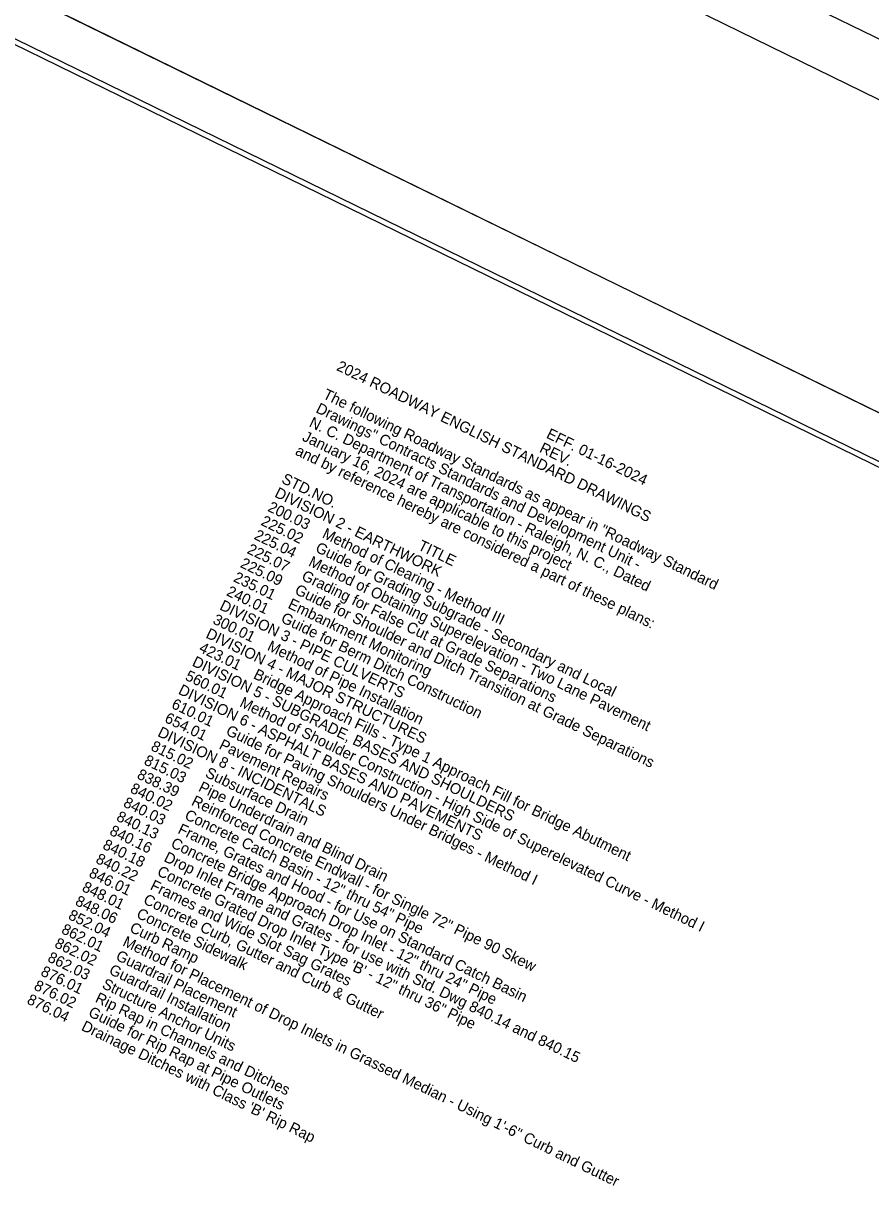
# Model space of a CAD drawing. Extents: x 1517888 to 1526099, y 633375 to 640181.
# Drawn here: x 1521738 to 1522517, y 634903 to 635991 of the extents above; entities that cross this region are included whole.
import ezdxf

# ---------------------------------------------------------------- set-up
doc = ezdxf.new("R2010")
doc.units = 0
for name, color, linetype in [('Default', 7, 'Continuous'), ('Sheet Cutting Line CELL', 7, 'Continuous'), ('Sheet Data Text CELL', 7, 'Continuous'), ('Sheet Plan CELL', 7, 'Continuous'), ('Sheet Plot Border Inside CELL', 7, 'Continuous'), ('Sheet Plot Border Outside CELL', 7, 'Continuous')]:
    doc.layers.add(name, color=color, linetype=linetype)

msp = doc.modelspace()

# ---------------------------------------------------------------- linework, layer by layer
at = {"layer": 'Default'}
msp.add_line((1521963.6, 636251.5), (1524989.1, 634771.8), dxfattribs=at)
at = {"layer": 'Sheet Cutting Line CELL'}
msp.add_line((1523118.1, 635342.8), (1520093.5, 636822.1), dxfattribs=at)
at = {"layer": 'Sheet Plan CELL'}
msp.add_lwpolyline([(1523067.8, 635317.3), (1520372.9, 636635.4), (1519450.2, 634748.9), (1522145.2, 633430.8)], close=True, dxfattribs=at)
at = {"layer": 'Sheet Plot Border Inside CELL'}
msp.add_lwpolyline([(1519172.2, 634879.3), (1522165.4, 633415.4), (1523092.5, 635310.8), (1520099.3, 636774.7)], close=True, dxfattribs=at)
at = {"layer": 'Sheet Plot Border Outside CELL'}
for points in [[(1525964.3, 636688.2), (1522938.8, 638168), (1521972.2, 636191.7), (1524997.7, 634712)], [(1519131.3, 634854.8), (1522155.9, 633375.5), (1523118.1, 635342.8), (1520093.5, 636822.1)]]:
    msp.add_lwpolyline(points, close=True, dxfattribs=at)

# ---------------------------------------------------------------- texts
at = {"layer": 'Sheet Data Text CELL'}
for s, p in [('2024 ROADWAY ENGLISH STANDARD DRAWINGS', (1522024.8, 635672.8)), ('The following Roadway Standards as appear in "Roadway Standard', (1522012.2, 635646.9)), ('Drawings" Contracts Standards and Development Unit -', (1522005.8, 635634)), ('N. C. Department of Transportation - Raleigh, N. C., Dated ', (1521999.5, 635621)), ('January 16, 2024 are applicable to this project', (1521993.2, 635608.1)), ('                                                      EFF. 01-16-2024', (1522037.5, 635698.7)), ('                                                      REV. ', (1522031.2, 635685.7)), ('and by reference hereby are considered a part of these plans:', (1521986.8, 635595.1)), ('STD.NO.                       TITLE', (1521974.2, 635569.2)), ('DIVISION 2 - EARTHWORK', (1521967.8, 635556.3)), ('200.03    Method of Clearing - Method III', (1521961.5, 635543.3)), ('225.02    Guide for Grading Subgrade - Secondary and Local', (1521955.2, 635530.4)), ('225.04    Method of Obtaining Superelevation - Two Lane Pavement', (1521948.9, 635517.5)), ('225.07    Grading for False Cut at Grade Separations', (1521942.5, 635504.5)), ('225.09    Guide for Shoulder and Ditch Transition at Grade Separations', (1521936.2, 635491.6)), ('235.01    Embankment Monitoring', (1521929.9, 635478.6)), ('240.01    Guide for Berm Ditch Construction', (1521923.5, 635465.7)), ('DIVISION 3 - PIPE CULVERTS', (1521917.2, 635452.7)), ('300.01    Method of Pipe Installation ', (1521910.9, 635439.8)), ('DIVISION 4 - MAJOR STRUCTURES', (1521904.5, 635426.8)), ('423.01    Bridge Approach Fills - Type 1 Approach Fill for Bridge Abutment', (1521898.2, 635413.9)), ('DIVISION 5 - SUBGRADE, BASES AND SHOULDERS', (1521891.9, 635401)), ('560.01    Method of Shoulder Construction - High Side of Superelevated Curve - Method I', (1521885.5, 635388)), ('DIVISION 6 - ASPHALT BASES AND PAVEMENTS', (1521879.2, 635375.1)), ('610.01    Guide for Paving Shoulders Under Bridges - Method I', (1521872.9, 635362.1)), ('654.01    Pavement Repairs', (1521866.6, 635349.2)), ('DIVISION 8 - INCIDENTALS', (1521860.2, 635336.2)), ('815.02    Subsurface Drain', (1521853.9, 635323.3)), ('815.03    Pipe Underdrain and Blind Drain', (1521847.6, 635310.3)), ('838.39    Reinforced Concrete Endwall - for Single 72" Pipe 90 Skew', (1521841.2, 635297.4)), ('840.02    Concrete Catch Basin - 12" thru 54" Pipe', (1521834.9, 635284.5)), ('840.03    Frame, Grates and Hood - for Use on Standard Catch Basin', (1521828.6, 635271.5)), ('840.13    Concrete Bridge Approach Drop Inlet - 12" thru 24" Pipe ', (1521822.2, 635258.6)), ('840.16    Drop Inlet Frame and Grates - for use with Std. Dwg 840.14 and 840.15', (1521815.9, 635245.6)), ('840.18    Concrete Grated Drop Inlet Type \'B\' - 12" thru 36" Pipe', (1521809.6, 635232.7)), ('840.22    Frames and Wide Slot Sag Grates', (1521803.2, 635219.7)), ('846.01    Concrete Curb, Gutter and Curb & Gutter', (1521796.9, 635206.8)), ('848.01    Concrete Sidewalk', (1521790.6, 635193.8)), ('848.06    Curb Ramp', (1521784.3, 635180.9)), ('852.04    Method for Placement of Drop Inlets in Grassed Median - Using 1\'-6" Curb and Gutter', (1521777.9, 635168)), ('862.01    Guardrail Placement', (1521771.6, 635155)), ('862.02    Guardrail Installation', (1521765.3, 635142.1)), ('862.03    Structure Anchor Units', (1521758.9, 635129.1)), ('876.01    Rip Rap in Channels and Ditches', (1521752.6, 635116.2)), ('876.02    Guide for Rip Rap at Pipe Outlets', (1521746.3, 635103.2)), ("876.04    Drainage Ditches with Class 'B' Rip Rap", (1521739.9, 635090.3))]:
    msp.add_text(s, height=10, rotation=333.9377, dxfattribs=at).set_placement(p)

doc.saveas('drawing.dxf')
